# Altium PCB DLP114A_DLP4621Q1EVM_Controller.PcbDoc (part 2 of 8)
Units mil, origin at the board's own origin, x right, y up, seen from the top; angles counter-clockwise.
Board outline 4803.15 x 2598.43 mil, 14 copper layers (Top Layer, GND 1, SIGNAL 1, GND 2, SIGNAL 2, PWR SPLIT PLANE 1, GND 3, GND 4, PWR SPLIT PLANE 2, SIGNAL 3, GND 5, SIGNAL 4, GND 6, Bottom Layer), stack 91.4 mil thick; 489 components, 394 nets, 1925 pads, 1273 vias.
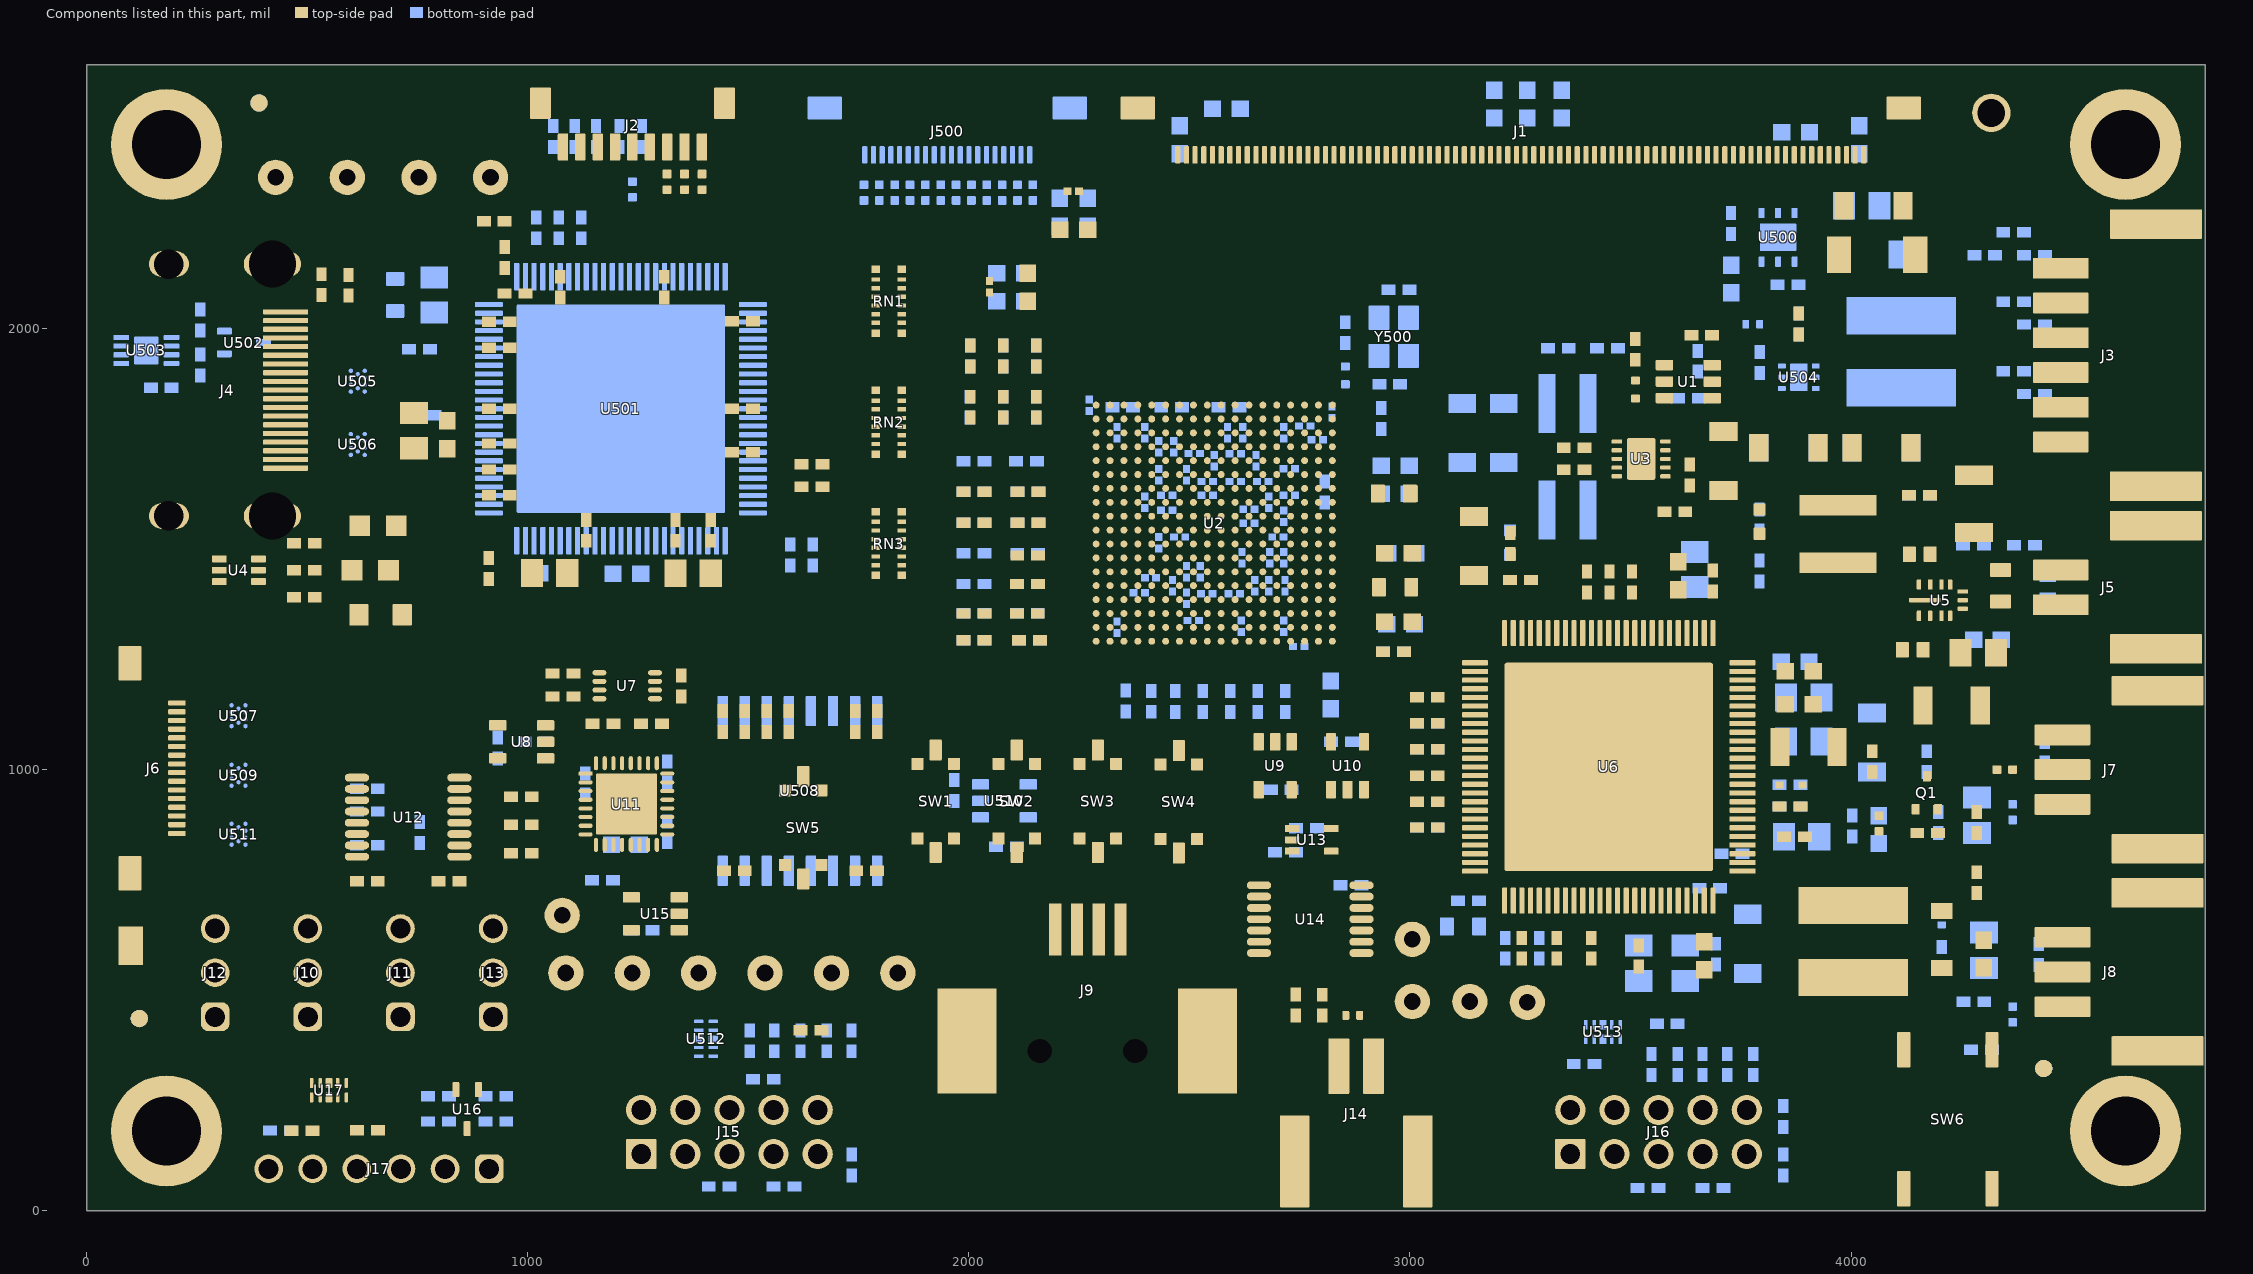
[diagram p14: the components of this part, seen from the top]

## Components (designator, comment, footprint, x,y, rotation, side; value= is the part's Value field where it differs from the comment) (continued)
R34 "CRCW0402150RFKED" 0402 493.55,1391.12 r180 top locked value=150
R35 "ERJ-2GEJ103X" 0402 2011.4,1354.08 r0 top locked value=10k
R36 "ERJ-2RKF33R0X" 0402 2132.51,1354.08 r180 top locked value=33.0
R37 "CRCW04022K20JNED" 0402 2011.4,1293.01 r180 top locked value=2.2k
R38 "CRCW04022K20JNED" 0402 2137.51,1293.01 r180 top locked value=2.2k
R39 "ERJ-2RKF33R0X" 0402 2962.37,1267.65 r180 top locked value=33.0
R40 "ERJ-2GEJ103X" 0402 1080.18,1218.07 r0 top locked value=10k
R41 "ERJ-2GEJ103X" 0402 3039.25,1163.8 r0 top locked value=10k
R42 "ERJ-2GEJ103X" 0402 1742.05,1109.51 r270 top locked value=10k
R43 "ERJ-2GEJ103X" 0402 1792.05,1109.51 r270 top locked value=10k
R44 "CRCW04023K30JNED" 0402 1442.05,1109.51 r270 top locked value=3.3k
R45 "ERJ-2GEJ103X" 0402 1542.05,1109.51 r270 top locked value=10k
R46 "CRCW04021K00FKED" 0402 1592.05,1109.51 r270 top locked value=1.00k
R47 "ERJ-2GEJ103X" 0402 3039.25,1105.2 r0 top locked value=10k
R48 "ERJ-2GEJ103X" 0402 1170.49,1104.45 r0 top locked value=10k
R49 "ERJ-2GEJ103X" 0402 1280.49,1104.45 r180 top locked value=10k
R50 "CRCW04021K00FKED" 0402 3039.25,1046.6 r0 top locked value=1.00k
R51 "ERJ-2RKF33R0X" 0402 985.47,939.01 r180 top locked value=33.0
R52 "ERJ-2GEJ103X" 0402 3039.25,927.58 r0 top locked value=10k
R53 "ERJ-2RKF33R0X" 0402 985.47,874.98 r180 top locked value=33.0
R54 "ERJ-2GEJ103X" 0402 3039.25,868.98 r0 top locked value=10k
R55 "ERJ2RKF1802X" 0402 4173.67,856.62 r0 top locked value=18.0k
R56 "ERJ-2RKF33R0X" 0402 985.47,810.94 r180 top locked value=33.0
R57 "CRCW040210R0FKED" 0402 4285.15,744 r90 top locked value=10.0
R58 "CRCW04023K30JNED" 0402 1768.43,770.93 r180 top locked value=3.3k
R59 "ERJ-2GEJ103X" 0402 1468.43,770.93 r180 top locked value=10k
R60 "ERJ-2GEJ103X" 0402 821.44,746.73 r180 top locked value=10k
R61 "ERJ-2GEJ103X" 0402 3253.82,595.29 r90 top locked value=10k
R62 "ERJ-2RKF33R0X" 0402 3332.56,595.29 r90 top locked value=33.0
R63 "ERJ-2GEJ103X" 0402 2741.35,466.78 r90 top locked value=10k
R64 "ERJ-2RKF33R0X" 0402 2801.2,466.34 r270 top locked value=33.0
R65 "ERJ-2GEJ103X" 0402 1642.03,409.02 r180 top locked value=10k
R500 "CRCW04020000Z0EDHP" 0402 3727.75,2237.97 r270 bottom locked value=0
R501 "ERJ-2GEJ103X" 0402 1121.46,2228.35 r90 bottom locked value=10k
R502 "ERJ-2GEJ103X" 0402 1070.46,2228.35 r90 bottom locked value=10k
R503 "ERJ-2GEJ103X" 0402 1019.46,2228.35 r90 bottom locked value=10k
R504 "CRCW04026K81FKED" 0402 4368.58,2218.21 r180 bottom locked value=6.81k
R505 "ERJ-2GEJ103X" 0402 3857.09,2098.95 r0 bottom locked value=10k
R506 "CRCW04026K81FKED" 0402 4368.58,2060.73 r180 bottom locked value=6.81k
R507 "CRCW04022K20JNED" 0402 257.96,2019.65 r90 bottom locked value=2.2k
R508 "CRCW040243K2FKED" 0402 3881.47,2010.55 r90 bottom locked value=43.2k
R509 "CRCW04021M00FKED" 0402 2853.2,1990.69 r90 bottom locked value=1.00Meg
R510 "ERJ-2GEJ103X" 0402 2152.78,1937.94 r270 bottom locked value=10k
R511 "ERJ-2GEJ103X" 0402 2077.78,1937.94 r270 bottom locked value=10k
R512 "ERJ-2GEJ103X" 0402 2002.79,1937.94 r270 bottom locked value=10k
R513 "ERJ-2RKF3603X" 0402 3336.29,1955.26 r180 bottom locked value=360k
R514 "RC0402FR-07180KL" 0402 3447.62,1955.24 r180 bottom locked value=180k
R515 "ERJ-2GEJ103X" 0402 754.84,1953.52 r180 bottom locked value=10k
R516 "CRCW04024R99FKED" 0402 3652.59,1926.01 r90 bottom locked value=4.99
R517 "CRCW04025K11FKED" 0402 3792.63,1923.29 r270 bottom locked value=5.11k
R518 "CRCW04022K20JNED" 0402 257.96,1917.22 r270 bottom locked value=2.2k
R519 "CRCW04026K81FKED" 0402 4368.58,1903.25 r180 bottom locked value=6.81k
R520 "3K" FP-ERJ-2RKF3001X_0402-MFG 2853.64,1893.84 r90 bottom locked value=3k
R521 "ERJ-2RKF33R0X" 0402 2152.78,1821.94 r90 bottom locked value=33.0
R522 "ERJ-2RKF33R0X" 0402 2077.78,1821.94 r90 bottom locked value=33.0
R523 "ERJ-2RKF33R0X" 0402 2002.26,1821.94 r90 bottom locked value=33.0
R524 "CRCW04020000Z0EDHP" 0402 3630.94,1842.39 r180 bottom locked value=0
R525 "CRCW040242K2FKED" 0402 2935.04,1795.96 r270 bottom locked value=42.2k
R526 "CRCW04022K20JNED" 0402 2589.91,1821.42 r180 bottom locked value=2.2k
R527 "CRCW040242K2FKED" 0402 2459.74,1821.42 r0 bottom locked value=42.2k
R528 "CRCW040242K2FKED" 0402 2348.83,1821.42 r0 bottom locked value=42.2k
R529 "ERJ-2GEJ103X" 0402 2130.79,1699.32 r0 bottom locked value=10k
R530 "ERJ-2RKF33R0X" 0402 2011.4,1699.32 r0 bottom locked value=33.0
R531 "CRCW04021K00FKED" 0402 2806.57,1629.75 r90 bottom locked value=1.00k
R532 "ERJ-2RKF33R0X" 0402 2133.94,1629.72 r180 bottom locked value=33.0
R533 "ERJ-2GEJ103X" 0402 2011.4,1629.72 r0 bottom locked value=10k
R534 "CRCW04020000Z0EDHP" 0402 4154.95,1622.25 r0 bottom locked value=0
R535 "ERJ-2GEJ104X" 0402 3792.3,1566.26 r90 bottom locked value=100k
R536 "ERJ-2GEJ103X" 0402 2133.94,1560.12 r0 bottom locked value=10k
R537 "ERJ-2GEJ103X" 0402 2011.4,1560.12 r0 bottom locked value=10k
R538 "ERJ-2RKF33R0X" 0402 1646.45,1486.66 r270 bottom locked value=33.0
R539 "ERJ-2RKF33R0X" 0402 1595.45,1486.66 r270 bottom locked value=33.0
R540 "CRCW0402511KFKED" 0402 4277.26,1508.87 r180 bottom locked value=511k
R541 "ERJ-2RKF1543X" 0402 4392.9,1508.4 r180 bottom locked value=154k
R542 "ERJ-2GEJ103X" 0402 2133.44,1490.52 r0 bottom locked value=10k
R543 "ERJ-2GEJ103X" 0402 2011.4,1490.52 r0 bottom locked value=10k
R544 "CRCW040243K2FKED" 0402 3792.3,1450.26 r90 bottom locked value=43.2k
R545 "ERJ-2GEJ103X" 0402 2132.8,1420.91 r0 bottom locked value=10k
R546 "ERJ-2RKF33R0X" 0402 2011.4,1420.91 r180 bottom locked value=33.0
R547 "ERJ-2GEJ103X" 0402 2011.4,1354.31 r0 bottom locked value=10k
R548 "ERJ-2GEJ103X" 0402 2132.51,1354.31 r0 bottom locked value=10k
R549 "CRCW04022K20JNED" 0402 2137.51,1293.01 r180 bottom locked value=2.2k
R550 "ERJ-2GEJ103X" 0402 2011.4,1293.01 r0 bottom locked value=10k
R551 "ERJ-2GEJ103X" 0402 2962.37,1267.65 r0 bottom locked value=10k
R552 "CRCW04022K20JNED" 0402 2355.62,1155.83 r270 bottom locked value=2.2k
R553 "CRCW04022K20JNED" 0402 2413.24,1154.98 r270 bottom locked value=2.2k
R554 "CRCW04021K00FKED" 0402 2467.76,1154.69 r90 bottom locked value=1.00k
R555 "ERJ-2RKF33R0X" 0402 2717.02,1154.69 r90 bottom locked value=33.0
R556 "CRCW04022K20JNED" 0402 2654.71,1154.69 r270 bottom locked value=2.2k
R557 "CRCW04022K20JNED" 0402 2592.39,1154.69 r270 bottom locked value=2.2k
R558 "CRCW04021K00FKED" 0402 2530.07,1154.69 r90 bottom locked value=1.00k
R559 "ERJ-2GEJ103X" 0402 3039.25,1105.2 r0 bottom locked value=10k
R560 "ERJ-2GEJ103X" 0402 1016.82,1063.12 r180 bottom locked value=10k
R561 "ERJ-2GEJ103X" 0402 3039.25,1046.6 r180 bottom locked value=10k
R562 "ERJ-2GEJ203X" 0402 4171.7,1018.12 r270 bottom locked value=20k
R563 "CRCW040230K0FKED" 0402 3861.41,965.59 r0 bottom locked value=30.0k
R564 "ERJ-2RKF33R0X" 0402 636.4,956.43 r0 bottom locked value=33.0
R565 "ERJ-2RKF1002X" 0402 3861.41,916.58 r180 bottom locked value=10.0k
R566 "CRCW0402162RFKED" 0402 4197.29,880.24 r270 bottom locked value=162
R567 "ERJ-2RKF33R0X" 0402 636.4,905.25 r0 bottom locked value=33.0
R568 "ERJ-2RKF33R0X" 0402 754.95,857.42 r270 bottom locked value=33.0
R569 "ERJ-2GEJ103X" 0402 3039.25,868.98 r0 bottom locked value=10k
R570 "ERJ-2GEJ103X" 0402 2717.98,812.52 r0 bottom value=10k
R571 "ERJ-2GEJ103X" 0402 2085.18,825.77 r0 bottom locked value=10k
R572 "ERJ-2GEJ103X" 0402 1169.56,749.74 r180 bottom locked value=10k
R573 "ERJ-2GEJ104X" 0402 3679.56,731.41 r0 bottom locked value=100k
R574 "ERJ-2GEJ103X" 0402 3293.19,595.29 r90 bottom locked value=10k
R575 "ERJ-2GEJ103X" 0402 3216.44,595.29 r90 bottom locked value=10k
R576 "CRCW040251K1FKED" 0402 3693.66,581.89 r90 bottom locked value=51.1k
R577 "CRCW04021K00FKED" 0402 4205.39,574.36 r270 bottom locked value=1.00k
R578 "CRCW040251K1FKED" 0402 4278.09,474.26 r0 bottom locked value=51.1k
R579 "ERJ-2GEJ103X" 0402 3583.18,423.69 r0 bottom locked value=10k
R580 "ERJ-2GEJ103X" 0402 1733.91,385.4 r90 bottom locked value=10k
R581 "CRCW040275R0FKED" 0402 1677.91,385.4 r90 bottom locked value=75.0
R582 "CRCW040275R0FKED" 0402 1618.4,385.4 r90 bottom locked value=75.0
R583 "CRCW040275R0FKED" 0402 1558.9,385.4 r90 bottom locked value=75.0
R584 "ERJ-2GEJ103X" 0402 1502.9,385.4 r90 bottom locked value=10k
R585 "CRCW04022K20JNED" 0402 4295.77,365.19 r180 bottom locked value=2.2k
R586 "CRCW040275R0FKED" 0402 3607.2,331.79 r90 bottom locked value=75.0
R587 "CRCW040275R0FKED" 0402 3547.48,331.79 r90 bottom locked value=75.0
R588 "CRCW040275R0FKED" 0402 3719.2,331.79 r90 bottom locked value=75.0
R589 "CRCW040275R0FKED" 0402 3663.2,331.79 r90 bottom locked value=75.0
R590 "ERJ-2GEJ103X" 0402 3778.03,331.77 r270 bottom locked value=10k
R591 "ERJ-2GEJ103X" 0402 3394.77,332.78 r0 bottom locked value=10k
R592 "CRCW04021K00FKED" 0402 927.67,259.94 r0 bottom locked value=1.00k
R593 "CRCW04021K00FKED" 0402 797.48,259.94 r180 bottom locked value=1.00k
RN1 "EXB-2HV330JV" RESCAXS_EXB-2HV 1818.38,2062.14 r270 top locked value=33
RN2 "EXB-2HV330JV" RESCAXS_EXB-2HV 1818.38,1787.47 r270 top locked value=33
RN3 "EXB-2HV330JV" RESCAXS_EXB-2HV 1818.38,1512.8 r270 top locked value=33
SW1 "CVS-01TB" FP-CVS-01TB_SMT_SW_4MM7_2MM0-MFG 1924.78,928.53 r0 top locked
SW2 "CVS-01TB" FP-CVS-01TB_SMT_SW_4MM7_2MM0-MFG 2108.66,928.53 r0 top locked
SW3 "CVS-01TB" FP-CVS-01TB_SMT_SW_4MM7_2MM0-MFG 2292.55,928.53 r0 top locked
SW4 "CVS-01TB" FP-CVS-01TB_SMT_SW_4MM7_2MM0-MFG 2476.09,927.34 r0 top locked
SW5 "CVS-01TB" FP-CVS-01TB_SMT_SW_4MM7_2MM0-MFG 1624.53,868.53 r0 top locked
SW6 "GT12MSABETR" FP-GT12MSABETR_SMT_7MM01_6MM93-MFG 4219.39,83.22 r90 top locked
TP1 "TESTPOINT" TESTPOINT 428.53,2342.8 r270 top locked
TP2 "TESTPOINT" TESTPOINT 590.93,2342.8 r270 top locked
TP3 "TESTPOINT" TESTPOINT 753.33,2342.8 r180 top locked
TP4 "TESTPOINT" TESTPOINT 915.73,2342.8 r180 top locked
TP5 "TESTPOINT" TESTPOINT 1078.22,669.94 r0 top locked
TP6 "TESTPOINT" TESTPOINT 3005.3,615.56 r0 top locked
TP7 "TESTPOINT" TESTPOINT 1086.46,539.32 r0 top locked
TP8 "TESTPOINT" TESTPOINT 1236.97,539.32 r90 top locked
TP9 "TESTPOINT" TESTPOINT 1387.48,539.32 r90 top locked
TP10 "TESTPOINT" TESTPOINT 1537.99,539.32 r0 top locked
TP11 "TESTPOINT" TESTPOINT 1688.5,539.32 r90 top locked
TP12 "TESTPOINT" TESTPOINT 1839.01,539.32 r90 top locked
TP13 "TESTPOINT" TESTPOINT 3005.3,474.4 r0 top locked
TP14 "TESTPOINT" TESTPOINT 3135.69,474.4 r90 top locked
TP15 "TESTPOINT" TESTPOINT 3266.08,472.65 r90 top locked
TP16 "S2751-46R" Harwin_S2751-46R 99.95,600.86 r90 top
TP17 "5007" Keystone5007 4317.81,2488.89 r0 top
U1 "TPS22918TDBVRQ1" DBV0006A_N 3630.94,1879.79 r180 top locked
U2 "DLPC231" ZEK0324A-MFG 2556.29,1558.89 r0 top locked
U3 "TPS62420QDRCRQ1" DRC0010J 3523.99,1704.49 r180 top locked
U4 "SN74LVC2G06QDCKRQ1" DCK0006A_N 345.17,1452.14 r0 top locked
U5 "LMR34215FAQRNX" RNX0012B 4197.98,1384.35 r90 top locked
U6 "TPS9900TPZPRQ1" PZP0100K 3450.67,1006.32 r0 top locked
U7 "TXS0102QDCURQ1" DCU0008A_N 1225.49,1190.38 r180 top locked
U8 "SN74LVC1G07QDBVRQ1" DBV0005A_N 986.31,1063.12 r180 top locked
U9 "74CBTLV1G125DBVRQ1" DBV0005A_N 2694.46,1008.97 r270 top locked
U10 "74CBTLV1G125DBVRQ1" DBV0005A_N 2858.34,1008.97 r90 top locked
U11 "CY7C65215-32LTXI" FP-CY7C65215-32LTXI_QFN32-IPC_C 1223.74,922.14 r0 top
U12 "SN74AVC4T774PWR" PW0016A_N 728.92,892.45 r180 top locked
U13 "SN74LVC1G04QDCKRQ1" DCK0005A_N 2777.19,841.06 r0 top locked
U14 "SN74LVC08AQPWRQ1" PW0014A_N 2773.82,661.12 r0 top locked
U15 "SN74LVC1G07QDBVRQ1" DBV0005A_N 1289.3,673.33 r180 top locked
U16 "TPD2E2U06QDCKRQ1" DCK0003A_N 862.58,230.65 r270 top locked
U17 "TPD4E05U06QDQARQ1" DQA0010A#1 549.37,273.45 r90 top locked
U500 "LP38693SD-3.3/NOPB" NGG0006A 3834.53,2206.85 r90 bottom locked
U501 "TFP401AIPZPRQ1" PZP0100H-MFG 1211.32,1818.32 r270 bottom locked
U502 "TPD2E2U06QDCKRQ1" DCK0003A_N 356.7,1968.44 r0 bottom locked
U503 "AT34C02D-MAHM-T" FP-AT34C02D-MAHM-T_UDFN8-MFG 135.48,1950.36 r0 bottom locked
U504 "TPS61170QDRVRQ1" DRV0006A 3881.47,1889.67 r0 bottom locked
U505 "PCMF2HDMI2SZ" FP-PCMF2HDMI2SZ_WLCSP10-MFG 614.77,1880.68 r270 bottom locked
U506 "PCMF2HDMI2SZ" FP-PCMF2HDMI2SZ_WLCSP10-MFG 614.77,1737.27 r270 bottom locked
U507 "PCMF2HDMI2SZ" FP-PCMF2HDMI2SZ_WLCSP10-MFG 344.42,1122.45 r270 bottom locked
U508 "MT25QL128ABA8ESF-0AAT" FP-MT25QL128ABA8ESF-0AAT_SOP2-16-MFG 1617.05,952.03 r270 bottom locked
U509 "PCMF2HDMI2SZ" FP-PCMF2HDMI2SZ_WLCSP10-MFG 344.42,987.44 r270 bottom locked
U510 "74CBTLV1G125DBVRQ1" DBV0005A_N 2080.49,929.27 r0 bottom locked
U511 "PCMF2HDMI2SZ" FP-PCMF2HDMI2SZ_WLCSP10-MFG 344.42,853.72 r270 bottom locked
U512 "TPD4E05U06QDQARQ1" DQA0010A#2 1404.29,389.93 r180 bottom locked
U513 "TPD4E05U06QDQARQ1" DQA0010A#2 3437.55,405.41 r90 bottom locked
Y500 "AM16070006" FP-AM16070006_SMT_XTAL_3MM2_2MM5-MFG 2963.05,1981.26 r270 bottom locked
ZZ1 "This Assembly Note is for PCB labels only" AssemblyNoteLabel 483.35,8777.95 r0 top
ZZ2 "These assemblies are ESD sensitive, ESD precautions shall be observed." AssemblyNote 483.35,8681.72 r0 top
ZZ3 "These assemblies must be clean and free from flux and all contaminants. Use of no clean flux is not acceptable." AssemblyNote 483.35,8585.49 r0 top
ZZ4 "These assemblies must comply with workmanship standards IPC-A-610 Class 2, unless otherwise specified." AssemblyNote 483.35,8489.26 r0 top
ZZ5 "Indication provided for the D* components at their cathode side." AssemblyNote 483.35,8393.03 r0 top

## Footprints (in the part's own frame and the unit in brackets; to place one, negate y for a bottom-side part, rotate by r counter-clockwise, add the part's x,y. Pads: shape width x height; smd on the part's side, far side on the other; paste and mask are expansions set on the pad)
0201_033 [mm] "SMD, 2-Leads, Height 0.33mm"
  rect 0.46x0.42 smd mask+0.048: 1(-0.33,0) 2(0.33,0)
  body extent -0.31,-0.16 0.31,0.16, height 0.33
0402 [mm] "0402 from SM-752 data"
  rect 0.8x0.6 smd: 1(-0.6,0) 2(0.6,0)
  silkscreen extent -1.22,-0.52 1.22,0.52, body extent -0.55,-0.3 0.55,0.3, height 0.6
0603 [mm] "0603 from SM-752 data"
  rect 1x0.95 smd: 1(-0.8,0) 2(0.8,0)
  silkscreen extent -1.52,-0.69 1.52,0.69, body extent -0.87,-0.47 0.87,0.47, height 1
0805_HV [mil] "0805 with 30mil clearance between pads"
  rect 50x63 smd: 1(-40,0) 2(40,0)
  silkscreen extent -74,-40 74,40, body extent -43,-29 43,29, height 57
1206_180 [mm] "1206_180"
  rect 1.1x1.6 smd: 1(-1.7,0) 2(1.7,0)
  silkscreen extent -0.9,-1 0.9,1, body extent -1.75,-0.95 1.75,0.95, height 1.8
1210_280 [mm] "SMD, 2-Leads, Body 3.6x2.8mm, Height 2.8mm"
  rect 1.1x2.2 smd: 1(-1.65,0) 2(1.65,0)
  silkscreen extent -0.84,-1.4 0.84,1.4, body extent -1.8,-1.4 1.8,1.4, height 2.8
AssemblyNote [mil] "Assembly Note"
AssemblyNoteLabel [mil] "Assembly Note for PCB Labels"
CDRH5D18 [mm] "Sumida recommended land pattern"
  rect 2.15x6.3 smd: 1(-2.075,0) 2(2.075,0)
  silkscreen extent -3.62,-3.56 3.64,3.57, body extent -3,-3 3,3, height 2
CE_Mark_5mm [mil] "Minimum text height for CE Mark"
  silkscreen extent -138,-98 138,98
CONN_USB-1734346 [mm] "TE Connectivity"
  rect 3x0.7 smd: 1(-3.5,1.9) 2(-3.5,-0.6) 3(-3.5,-1.85) 4(-3.5,0.65)
  rect 6.04x3.4 smd: 5(2.92,-6.92) 6(2.92,6.92)
  round 1 hole 1.4 unplated: MH1(3.5,2.75) MH2(3.5,-2.75)
  silkscreen extent -3.8,-6.4 12.7,6.4, body extent -4.6,-8.22 12.5,8.28, height 11.31
DBV0005A_N [mm] "SOT23, 5-Leads, Body 2.9x1.6mm, Pitch 0.95mm, Lead Span 2.8mm, IPC Medium Density"
  rrect17% 1x0.6 smd: 1(-1.375,0.95) 2(-1.375,0) 3(-1.375,-0.95) 4(1.375,-0.95) 5(1.375,0.95)
  silkscreen extent -1.63,-1.55 0.38,1.55, body extent -1.42,-1.46 1.42,1.46, height 1.09
DBV0006A_N [mm] "SOT23, 6-Leads, Body 2.9x1.6mm, Pitch 0.95mm, Lead Span 2.8mm, IPC Medium Density"
  rrect17% 1x0.6 smd: 1(-1.375,0.95) 2(-1.375,0) 3(-1.375,-0.95) 4(1.375,-0.95) 5(1.375,0) 6(1.375,0.95)
  silkscreen extent -1.67,-1.55 0.5,1.55, body extent -1.42,-1.46 1.42,1.46, height 1.12
DCK0003A_N [mm] "SOT23, 3-Leads, Body 2.0x1.25mm, Pitch 0.65mm, Lead Span 2.1mm, IPC Medium Density"
  rrect25% 0.85x0.4 smd: 1(-1.125,0.65) 2(-1.125,-0.65) 3(1.125,0)
  silkscreen extent -1.02,-1.1 0.7,1.53, body extent -1.06,-1 1.06,1, height 1.1
DCK0005A_N [mm] "SOT353, 5-Leads, Body 2x1.3mm, Pitch 0.65mm, Lead Span 2.1mm, IPC Medium Density"
  rrect25% 0.85x0.4 smd: 1(-1.125,0.65) 2(-1.125,0) 3(-1.125,-0.65) 4(1.125,-0.65) 5(1.125,0.65)
  silkscreen extent -1.48,-1.02 0.55,1.1, body extent -1.14,-1 1.14,1, height 0.95
DCK0006A_N [mm] "SOT23, 6-Leads, Body 2x1.3mm, Pitch 0.65mm, Lead Span 2.1mm, IPC Medium Density"
  rrect25% 0.85x0.4 smd: 1(-1.125,0.65) 2(-1.125,0) 3(-1.125,-0.65) 4(1.125,-0.65) 5(1.125,0) 6(1.125,0.65)
  silkscreen extent -1.5,-1.09 0.51,1.09, body extent -1.14,-1 1.14,1, height 0.95
DCU0008A_N [mm] "TSSOP, 8-Leads, Body 2x2.3mm, Pitch 0.5mm, IPC Medium Density"
  oval 0.8x0.3 smd: 1(-1.6,0.75) 2(-1.6,0.25) 3(-1.6,-0.25) 4(-1.6,-0.75) 5(1.6,-0.75) 6(1.6,-0.25) 7(1.6,0.25) 8(1.6,0.75)
  silkscreen extent -1.05,-1.05 0.38,1.05, body extent -1.56,-1 1.56,1, height 0.9
DQA0010A#1 [mm] "SON, 10-Leads, Body 1x2.5mm, Pitch 0.5mm, TI Recommended"
  rrect50% 0.565x0.2 smd: 1(-0.417,1) 2(-0.417,0.5) 4(-0.417,-0.5) 5(-0.417,-1) 6(0.417,-1) 7(0.417,-0.5) 9(0.417,0.5) 10(0.417,1)
  rrect28% 0.565x0.36 on Top Paste: 3(-0.417,0) 8(0.417,0)
  rrect25% 0.565x0.4 smd paste-0.2: 3(-0.417,0) 8(0.417,0)
  silkscreen extent -0.67,-1.45 0.55,1.45, body extent -0.55,-1.3 0.55,1.3, height 0.56
DQA0010A#2 [mm] "SON, 10-Leads, Body 1x2.5mm, Pitch 0.5mm, TI Recommended"
  rrect50% 0.565x0.2 smd: 1(-0.417,1) 2(-0.418,0.5) 4(-0.418,-0.5) 5(-0.417,-1) 6(0.417,-1) 7(0.418,-0.5) 9(0.417,0.5) 10(0.417,1)
  rrect28% 0.565x0.36 on Bottom Paste: 3(-0.418,0) 8(0.417,0)
  rrect25% 0.565x0.4 smd paste-0.2: 3(-0.418,0) 8(0.417,0)
  silkscreen extent -0.67,-1.45 0.55,1.45, body extent -0.55,-1.3 0.55,1.3, height 0.56
DRC0010J [mm] "VSON-10"
  rrect42% 0.6x0.24 smd: 1(-1.4,1) 2(-1.4,0.5) 3(-1.4,0) 4(-1.4,-0.5) 5(-1.4,-1) 6(1.4,-1) 7(1.4,-0.5) 8(1.4,0) 9(1.4,0.5) 10(1.4,1)
  rrect12% 1.65x2.4 smd paste-1 mask-2: 11(0,0)
  Top Layer region: -0.375,-1.65 -0.375,-1.2 -0.775,-1.2 -0.794,-1.196 -0.81,-1.185 -0.821,-1.169 -0.825,-1.15 -0.825,-1.15 -0.825,1.15 -0.821,1.169 -0.81,1.185 -0.794,1.196 -0.775,1.2 -0.775,1.2 -0.375,1.2 -0.375,1.65 -0.371,1.669 -0.36,1.685 -0.344,1.696 -0.325,1.7 -0.325,1.7 -0.325,1.7 -0.175,1.7 -0.175,1.7 -0.156,1.696 -0.14,1.685 -0.129,1.669 -0.125,1.65 -0.125,1.65 -0.125,1.2 0.125,1.2 0.125,1.65 0.129,1.669 0.14,1.685 0.156,1.696 0.175,1.7 0.175,1.7 0.175,1.7 0.325,1.7 0.325,1.7 0.344,1.696 0.36,1.685 0.371,1.669 0.375,1.65 0.375,1.65 0.375,1.2 0.775,1.2 0.794,1.196 0.81,1.185 0.821,1.169 0.825,1.15 0.825,1.15 0.825,-1.15 0.821,-1.169 0.81,-1.185 0.794,-1.196 0.775,-1.2 0.775,-1.2 0.375,-1.2 0.375,-1.65 0.371,-1.669 0.36,-1.685 0.344,-1.696 0.325,-1.7 0.325,-1.7 0.175,-1.7 0.156,-1.696 0.14,-1.685 0.129,-1.669 0.125,-1.65 0.125,-1.65 0.125,-1.2 -0.125,-1.2 -0.125,-1.65 -0.129,-1.669 -0.14,-1.685 -0.156,-1.696 -0.175,-1.7 -0.175,-1.7 -0.325,-1.7 -0.344,-1.696 -0.36,-1.685 -0.371,-1.669 -0.375,-1.65
  body extent -1.5,-1.5 1.5,1.5, height 1
DRV0006A [mm] "SON, 6-Leads, Body 2x2mm, Pitch 0.65mm, Thermal Pad 1.6x1mm, TI Recommended"
  rrect33% 0.45x0.3 smd: 1(-0.975,0.65) 2(-0.975,0) 3(-0.975,-0.65) 4(0.975,-0.65) 5(0.975,0) 6(0.975,0.65)
  rrect14% 1x0.7 on Bottom Paste: 7(0,-0.45) 7(0,0.45)
  rrect10% 1x1.6 smd paste-0.5: 7(0,0)
  silkscreen extent -1.05,-1.2 1.05,1.2, body extent -1.05,-1.05 1.05,1.05, height 0.81
ESD_Overlay_Small [mil]
  silkscreen extent -62,-48 64,61
FCC_disclaimer [mil]
Fiducial10-20 [mm]
  round 1 smd mask+0.5: 1(0,0)
  Top Layer keep-out circle w1.178: c0,0 r0.5
FP-501331-0907_HDR9-MFG [mm]
  rrect17% 0.6x1.55 smd paste+0 mask+0: 1(4,2.41) 2(3,2.41) 3(2,2.41) 4(1,2.41) 5(0,2.41) 6(-1,2.41) 7(-2,2.41) 8(-3,2.41) 9(-4,2.41)
  rrect8% 1.2x1.8 smd paste+0 mask+0: 10(-5.3,-0.115) 11(5.3,-0.115)
  silkscreen extent -5.6,-2.33 5.6,3.86, body extent -5.62,-2.24 5.62,2.83, height 5.6
FP-502352-0200_HDR2-MFG [mm]
  rrect8% 1.2x3.2 smd paste+0 mask+0: 1(-1,3.53) 2(1,3.53)
  rrect6% 1.7x5.3 smd paste+0 mask+0: 3(-3.55,-1.95) 4(3.55,-1.95)
  body extent -4,-4.7 4,4.7, height 6.6
FP-505110-1692_CONN_SMT_12MM7_5MM25-MFG [mm]
  rrect33% 0.3x1 smd paste+0 mask+0: 1(-3.75,2.475) 2(-3.25,2.475) 3(-2.75,2.475) 4(-2.25,2.475) 5(-1.75,2.475) 6(-1.25,2.475) 7(-0.75,2.475) 8(-0.25,2.475) 9(0.25,2.475) 10(0.75,2.475) 11(1.25,2.475) 12(1.75,2.475) 13(2.25,2.475) 14(2.75,2.475) 15(3.25,2.475) 16(3.75,2.475)
  rrect8% 2x1.3 smd paste+0 mask+0: 17(-6.05,-0.225) 18(6.05,-0.225)
  body extent -6.75,-2.63 6.75,2.67, height 1.9
FP-702461002_HDR10-MFG [mm]
  rrect6% 1.74x1.74 hole 1.14 paste-1000 mask+0: 1(-5.08,-1.275)
  round 1.74 hole 1.14 paste-1000 mask+0: 2(-5.08,1.265) 3(-2.54,-1.275) 4(-2.54,1.265) 5(0,-1.275) 6(0,1.265) 7(2.54,-1.275) 8(2.54,1.265) 9(5.08,-1.275) 10(5.08,1.265)
  silkscreen extent -10.26,-5.34 10.26,4.54, body extent -10.16,-4.45 10.16,4.44, height 9.47
FP-5023520200_HDR2-MFG [mm]
  rrect8% 1.2x3.2 smd paste+0 mask+0: 1(-1,3.53) 2(1,3.53)
  rrect6% 1.7x5.3 smd paste+0 mask+0: 3(-3.55,-1.95) 4(3.55,-1.95)
  silkscreen extent -4.1,-4.8 4.1,5.85, body extent -4,-4.7 4,4.7, height 6.6
FP-5023520600_HDR6-MFG [mm]
  rrect8% 1.2x3.2 smd paste+0 mask+0: 1(-5,3.53) 2(-3,3.53) 3(-1,3.53) 4(1,3.53) 5(3,3.53) 6(5,3.53)
  rrect6% 1.7x5.3 smd paste+0 mask+0: 7(-7.55,-1.95) 8(7.55,-1.95)
  silkscreen extent -8.13,1.07 8.13,5.72, body extent -8,-4.7 8,4.7, height 6.6
FP-5051102091_CONN_FFC_FPC20-MFG [mm]
  rrect33% 0.3x1 smd paste+0 mask+0: 1(-4.75,0.91) 2(-4.25,0.91) 3(-3.75,0.91) 4(-3.25,0.91) 5(-2.75,0.91) 6(-2.25,0.91) 7(-1.75,0.91) 8(-1.25,0.91) 9(-0.75,0.91) 10(-0.25,0.91) 11(0.25,0.91) 12(0.75,0.91) 13(1.25,0.91) 14(1.75,0.91) 15(2.25,0.91) 16(2.75,0.91) 17(3.25,0.91) 18(3.75,0.91) 19(4.25,0.91) 20(4.75,0.91)
  rrect8% 2x1.3 smd paste+0 mask+0: 21(-7.05,-1.79) 22(7.05,-1.79)
  silkscreen extent -7.45,-4.29 7.45,2.08, body extent -7.75,-4.19 7.75,1.11, height 2.1
FP-5051108091_CONN_FFC_FPC_80-MFG [mm]
  rrect33% 0.3x1 smd paste+0 mask+0: 1(-19.75,2.475) 2(-19.25,2.475) 3(-18.75,2.475) 4(-18.25,2.475) 5(-17.75,2.475) 6(-17.25,2.475) 7(-16.75,2.475) 8(-16.25,2.475) 9(-15.75,2.475) 10(-15.25,2.475) 11(-14.75,2.475) 12(-14.25,2.475) 13(-13.75,2.475) 14(-13.25,2.475) 15(-12.75,2.475) 16(-12.25,2.475) 17(-11.75,2.475) 18(-11.25,2.475) 19(-10.75,2.475) 20(-10.25,2.475) 21(-9.75,2.475) 22(-9.25,2.475) 23(-8.75,2.475) 24(-8.25,2.475) 25(-7.75,2.475) 26(-7.25,2.475) 27(-6.75,2.475) 28(-6.25,2.475) 29(-5.75,2.475) 30(-5.25,2.475) 31(-4.75,2.475) 32(-4.25,2.475) 33(-3.75,2.475) 34(-3.25,2.475) 35(-2.75,2.475) 36(-2.25,2.475) 37(-1.75,2.475) 38(-1.25,2.475) 39(-0.75,2.475) 40(-0.25,2.475) 41(0.25,2.475) 42(0.75,2.475) 43(1.25,2.475) 44(1.75,2.475) 45(2.25,2.475) 46(2.75,2.475) 47(3.25,2.475) 48(3.75,2.475) 49(4.25,2.475) 50(4.75,2.475) 51(5.25,2.475) 52(5.75,2.475) 53(6.25,2.475) 54(6.75,2.475) 55(7.25,2.475) 56(7.75,2.475) 57(8.25,2.475) 58(8.75,2.475) 59(9.25,2.475) 60(9.75,2.475) 61(10.25,2.475) 62(10.75,2.475) 63(11.25,2.475) 64(11.75,2.475) 65(12.25,2.475) 66(12.75,2.475) 67(13.25,2.475) 68(13.75,2.475) 69(14.25,2.475) 70(14.75,2.475) 71(15.25,2.475) 72(15.75,2.475) 73(16.25,2.475) 74(16.75,2.475) 75(17.25,2.475) 76(17.75,2.475) 77(18.25,2.475) 78(18.75,2.475) 79(19.25,2.475) 80(19.75,2.475)
  rrect8% 2x1.3 smd paste+0 mask+0: 81(-22.05,-0.225) 82(22.05,-0.225)
  silkscreen extent -22.45,-2.73 22.45,3.65, body extent -22.75,-2.63 22.75,2.68, height 2.1
FP-AM16070006_SMT_XTAL_3MM2_2MM5-MFG [mm]
  rrect8% 1.4x1.2 smd paste+0 mask+0: 1(-1.1,-0.85) 2(1.1,-0.85) 3(1.1,0.85) 4(-1.1,0.85)
  body extent -1.6,-1.25 1.6,1.25, height 0.8
FP-AT34C02D-MAHM-T_UDFN8-MFG [mm]
  rrect33% 0.9x0.3 smd paste+0 mask+0: 1(-1.45,0.75) 2(-1.45,0.25) 3(-1.45,-0.25) 4(-1.45,-0.75) 5(1.45,-0.75) 6(1.45,-0.25) 7(1.45,0.25) 8(1.45,0.75)
  rrect7% 1.4x1.6 smd paste+0 mask+0: 9(0,0)
  silkscreen extent -2.6,-1.3 1.55,1.3, body extent -1.51,-1 1.51,1, height 0.6
FP-C0603C223K1RACAUTO_0603-MFG [mm]
  rrect13% 0.75x0.9 smd paste+0 mask+0: 1(-0.6,0) 2(0.6,0)
  silkscreen extent -0.87,-0.85 0.88,0.85, body extent -1.2,-0.6 1.2,0.6, height 0.25
FP-CGA3E2C0G1H330J080AA_0603-MFG [mm]
  rrect14% 0.7x0.7 smd paste+0 mask+0: 1(-0.7,0) 2(0.7,0)
  silkscreen extent -0.95,-0.73 0.95,0.73, body extent -1.15,-0.65 1.15,0.65, height 0.25
FP-CGA4J1X7R0J106K125AC_0805-MFG [mm]
  rrect13% 0.8x1.05 smd paste+0 mask+0: 1(-0.925,0) 2(0.925,0)
  silkscreen extent -0.15,-0.73 0.15,0.73, body extent -1,-0.63 1,0.63, height 1.45
FP-CVS-01TB_SMT_SW_4MM7_2MM0-MFG [mm]
  rrect14% 0.7x1.2 smd paste+0 mask+0: 1(0,2.95) 2(0,-2.95)
  rrect14% 0.7x0.7 smd paste+0 mask+0: 3(-1.05,2.15) 4(1.05,2.15) 5(-1.05,-2.15) 6(1.05,-2.15)
  silkscreen extent -1.15,-1.43 1.15,4.22, body extent -1.5,-3.65 1.5,3.65, height 0.25
FP-CY7C65215-32LTXI_QFN32-IPC_C [mm]
  rrect42% 0.81x0.239 smd paste+0 mask+0: 1(-2.351,1.75)
  rrect100% 0.81x0.239 smd paste+0 mask+0: 2(-2.351,1.25) 3(-2.351,0.75) 4(-2.351,0.25) 5(-2.351,-0.25) 6(-2.351,-0.75) 7(-2.351,-1.25) 8(-2.351,-1.75) 17(2.351,-1.75) 18(2.351,-1.25) 19(2.351,-0.75) 20(2.351,-0.25) 21(2.351,0.25) 22(2.351,0.75) 23(2.351,1.25) 24(2.351,1.75)
  rrect100% 0.239x0.81 smd paste+0 mask+0: 9(-1.75,-2.351) 10(-1.25,-2.351) 11(-0.75,-2.351) 12(-0.25,-2.351) 13(0.25,-2.351) 14(0.75,-2.351) 15(1.25,-2.351) 16(1.75,-2.351) 25(1.75,2.351) 26(1.25,2.351) 27(0.75,2.351) 28(0.25,2.351) 29(-0.25,2.351) 30(-0.75,2.351) 31(-1.25,2.351) 32(-1.75,2.351)
  rrect3% 3.5x3.5 smd paste-1000 mask+0: 33(0,0)
  silkscreen extent -3.33,-2.5 2.5,2.5, body extent -2.86,-2.86 2.86,2.86, height 0.25
FP-ERJ-2RKF3000X_0402-MFG [mm]
  rrect21% 0.475x0.5 smd paste+0 mask+0: 1(-0.513,0) 2(0.513,0)
  silkscreen extent -0.52,-0.63 0.53,0.63, body extent -0.85,-0.38 0.85,0.38, height 0.25
FP-ERJ-2RKF3001X_0402-MFG [mm]
  rrect21% 0.475x0.5 smd paste+0 mask+0: 1(-0.513,0) 2(0.513,0)
  silkscreen extent -0.53,-0.63 0.53,0.63, body extent -0.5,-0.25 0.5,0.25, height 0.4
FP-GCM155R71H103KA55D_0402-MFG [mm]
  rrect25% 0.4x0.5 smd paste+0 mask+0: 1(-0.4,0) 2(0.4,0)
  silkscreen extent -0.53,-0.65 0.53,0.65, body extent -0.5,-0.25 0.5,0.25, height 0.55
FP-GT12MSABETR_SMT_7MM01_6MM93-MFG [mil]
  rrect13% 80x30 smd paste+0 mask+0: 1(281.96,-100) 3(281.96,100) 4(-33,100) 5(-33,-100)
  silkscreen extent -61,-138 349,138, body extent -215,-142 326,142, height 10
FP-HD04-19-TH-TR_CONN_HDMI_RCPT19-MFG [mm]
  rrect33% 0.3x2.6 smd paste+0 mask+0: 1(4.5,5.56) 2(4,5.56) 3(3.5,5.56) 4(3,5.56) 5(2.5,5.56) 6(2,5.56) 7(1.5,5.56) 8(1,5.56) 9(0.5,5.56) 10(0,5.56) 11(-0.5,5.56) 12(-1,5.56) 13(-1.5,5.56) 14(-2,5.56) 15(-2.5,5.56) 16(-3,5.56) 17(-3.5,5.56) 18(-4,5.56) 19(-4.5,5.56)
  rrect100% 1.5x3.3 hole 2.7 slot 0.9 at 0 deg paste-1000 mask+0: 20(-7.25,4.8) 21(7.25,4.8)
  rrect100% 1.5x2.3 hole 1.7 slot 0.9 at 0 deg paste-1000 mask+0: 22(-7.25,-1.16) 23(7.25,-1.16)
  silkscreen extent -7.75,-5.9 7.75,7.63, body extent -7.5,-5.8 7.5,6.4, height 6.46
FP-LTST-C171KRKT_0805-MFG [mm]
  rrect9% 1.1x1.25 smd paste+0 mask+0: 1(-1.25,0) 2(1.25,0)
  silkscreen extent -2.52,-0.68 0.33,0.67, body extent -1.9,-0.78 1.9,0.77, height 0.25
FP-MMZ1005Y121CTD25_0402-MFG [mm]
  rrect20% 0.5x0.5 smd paste+0 mask+0: 1(-0.45,0) 2(0.45,0)
  body extent -0.5,-0.25 0.5,0.25, height 0.55
FP-MPZ2012S101ATD25_0805-MFG [mm]
  rrect13% 0.8x1.2 smd paste+0 mask+0: 1(-0.9,0) 2(0.9,0)
  silkscreen extent -0.13,-0.73 0.13,0.73, body extent -1.4,-0.82 1.4,0.82, height 0.25
FP-MT25QL128ABA8ESF-0AAT_SOP2-16-MFG [mm]
  rrect17% 1.75x0.6 smd paste+0 mask+0: 1(-4.6,4.445) 2(-4.6,3.175) 3(-4.6,1.905) 4(-4.6,0.635) 5(-4.6,-0.635) 6(-4.6,-1.905) 7(-4.6,-3.175) 8(-4.6,-4.445) 9(4.6,-4.445) 10(4.6,-3.175) 11(4.6,-1.905) 12(4.6,-0.635) 13(4.6,0.635) 14(4.6,1.905) 15(4.6,3.175) 16(4.6,4.445)
  body extent -5.16,-5.15 5.16,5.15, height 2.65
FP-PCMF2HDMI2SZ_WLCSP10-MFG [mm]
  round 0.25 smd paste+0 mask-1000: A1(-0.6,0.4) A2(-0.2,0.4) A3(0.2,0.4) A4(0.6,0.4) B1(-0.4,0) B2(0.4,0) C1(-0.6,-0.4) C2(-0.2,-0.4) C3(0.2,-0.4) C4(0.6,-0.4)
  silkscreen extent -1.1,-0.9 1.1,1.5, body extent -0.78,-0.59 0.78,0.59, height 0.6
FP-SZMM5Z6V2T1G_SOD523-MFG [mm]
  rrect25% 0.48x0.4 smd paste+0 mask+0: 1(-0.66,0) 2(0.66,0)
  silkscreen extent -1.62,-0.45 0.05,0.45, body extent -1,-0.55 1,0.55, height 0.25
Harwin_S2751-46R [mm] "Test Point, SMT"
  rect 2.2x1.4 smd: 1(0,0)
  body extent -1,-0.6 1,0.6, height 1.4
Keystone5007 [mil] "Keystone Compact loops"
  round 87 hole 63: 1(0,0)
  silkscreen extent -70,-70 70,70, body extent -63,-63 62,63, height 225
LED_LTST-C171 [mm] "LITE-ON"
  rect 1.2x1.2 smd: 1(-1.05,0) 2(1.05,0)
  silkscreen extent -1.6,-1 2.2,1, body extent -1.05,-0.68 1.05,0.67, height 0.8
Molex_502352-0300 [mm] "Header(shrouded), 2mm, 3x1, R/A, SMT"
  rrect8% 1.2x3.2 smd: 1(-2,3.53) 2(0,3.53) 3(2,3.53)
  rrect6% 1.7x5.3 smd: MP1(-4.55,-1.95) MP2(4.55,-1.95)
  silkscreen extent -5,-4.7 5,5, body extent -5,-4.7 5,4.7, height 6.46
MTGP_252mil_157mil_6Via [mil] "4-40 Mounting Hole, Plated, for Pan Head"
  round 252 hole 157: 1(0,0)
NGG0006A [mm] "TI recommended footprint"
  rrect29% 0.6x0.35 smd: 1(-1.4,0.95) 2(-1.4,0) 3(-1.4,-0.95) 4(1.4,-0.95) 5(1.4,0) 6(1.4,0.95)
  rrect11% 1.47x0.94 on Bottom Paste: 7(0,0.57) 7(0,-0.57)
  rrect6% 1.6x2.1 smd paste-1: 7(0,0)
  silkscreen extent -1.65,-1.65 1.65,1.65, body extent -1.5,-1.5 1.5,1.5, height 0.81
PW0014A_N [mm] "TSOP, 14-Leads, Body 5x4.4mm, Pitch 0.65mm, IPC Medium Density"
  oval 1.4x0.45 smd: 1(-2.95,1.95) 2(-2.95,1.3) 3(-2.95,0.65) 4(-2.95,0) 5(-2.95,-0.65) 6(-2.95,-1.3) 7(-2.95,-1.95) 8(2.95,-1.95) 9(2.95,-1.3) 10(2.95,-0.65) 11(2.95,0) 12(2.95,0.65) 13(2.95,1.3) 14(2.95,1.95)
  silkscreen extent -3.4,-2.55 1.85,2.55, body extent -3.21,-2.5 3.21,2.5, height 1
PW0016A_N [mm] "TSOP, 16-Leads, Body 5x4.4mm, Pitch 0.65mm, IPC Medium Density"
  oval 1.4x0.45 smd: 1(-2.95,2.275) 2(-2.95,1.625) 3(-2.95,0.975) 4(-2.95,0.325) 5(-2.95,-0.325) 6(-2.95,-0.975) 7(-2.95,-1.625) 8(-2.95,-2.275) 9(2.95,-2.275) 10(2.95,-1.625) 11(2.95,-0.975) 12(2.95,-0.325) 13(2.95,0.325) 14(2.95,0.975) 15(2.95,1.625) 16(2.95,2.275)
  silkscreen extent -3.5,-2.55 1.85,2.75, body extent -3.21,-2.5 3.21,2.5, height 1
PZP0100H-MFG [mm]
  rrect33% 1.6x0.3 smd paste-1000 mask+0: 1(-7.6,6) 2(-7.6,5.5) 3(-7.6,5) 4(-7.6,4.5) 5(-7.6,4) 6(-7.6,3.5) 7(-7.6,3) 8(-7.6,2.5) 9(-7.6,2) 10(-7.6,1.5) 11(-7.6,1) 12(-7.6,0.5) 13(-7.6,0) 14(-7.6,-0.5) 15(-7.6,-1) 16(-7.6,-1.5) 17(-7.6,-2) 18(-7.6,-2.5) 19(-7.6,-3) 20(-7.6,-3.5) 21(-7.6,-4) 22(-7.6,-4.5) 23(-7.6,-5) 24(-7.6,-5.5) 25(-7.6,-6) 51(7.6,-6) 52(7.6,-5.5) 53(7.6,-5) 54(7.6,-4.5) 55(7.6,-4) 56(7.6,-3.5) 57(7.6,-3) 58(7.6,-2.5) 59(7.6,-2) 60(7.6,-1.5) 61(7.6,-1) 62(7.6,-0.5) 63(7.6,0) 64(7.6,0.5) 65(7.6,1) 66(7.6,1.5) 67(7.6,2) 68(7.6,2.5) 69(7.6,3) 70(7.6,3.5) 71(7.6,4) 72(7.6,4.5) 73(7.6,5) 74(7.6,5.5) 75(7.6,6)
  rrect33% 0.3x1.6 smd paste-1000 mask+0: 26(-6,-7.6) 27(-5.5,-7.6) 28(-5,-7.6) 29(-4.5,-7.6) 30(-4,-7.6) 31(-3.5,-7.6) 32(-3,-7.6) 33(-2.5,-7.6) 34(-2,-7.6) 35(-1.5,-7.6) 36(-1,-7.6) 37(-0.5,-7.6) 38(0,-7.6) 39(0.5,-7.6) 40(1,-7.6) 41(1.5,-7.6) 42(2,-7.6) 43(2.5,-7.6) 44(3,-7.6) 45(3.5,-7.6) 46(4,-7.6) 47(4.5,-7.6) 48(5,-7.6) 49(5.5,-7.6) 50(6,-7.6) 76(6,7.6) 77(5.5,7.6) 78(5,7.6) 79(4.5,7.6) 80(4,7.6) 81(3.5,7.6) 82(3,7.6) 83(2.5,7.6) 84(2,7.6) 85(1.5,7.6) 86(1,7.6) 87(0.5,7.6) 88(0,7.6) 89(-0.5,7.6) 90(-1,7.6) 91(-1.5,7.6) 92(-2,7.6) 93(-2.5,7.6) 94(-3,7.6) 95(-3.5,7.6) 96(-4,7.6) 97(-4.5,7.6) 98(-5,7.6) 99(-5.5,7.6) 100(-6,7.6)
  rrect1% 12x12 smd paste-1000 mask-1000: 101(0,0)
  silkscreen extent -9.05,-7.1 7.1,7.1, body extent -8.01,-8.01 8.01,8.01, height 1.2
PZP0100K [mm] "TQFP-100"
  rrect33% 1.5x0.3 smd: 1(-7.7,6) 2(-7.7,5.5) 3(-7.7,5) 4(-7.7,4.5) 5(-7.7,4) 6(-7.7,3.5) 7(-7.7,3) 8(-7.7,2.5) 9(-7.7,2) 10(-7.7,1.5) 11(-7.7,1) 12(-7.7,0.5) 13(-7.7,0) 14(-7.7,-0.5) 15(-7.7,-1) 16(-7.7,-1.5) 17(-7.7,-2) 18(-7.7,-2.5) 19(-7.7,-3) 20(-7.7,-3.5) 21(-7.7,-4) 22(-7.7,-4.5) 23(-7.7,-5) 24(-7.7,-5.5) 25(-7.7,-6) 51(7.7,-6) 52(7.7,-5.5) 53(7.7,-5) 54(7.7,-4.5) 55(7.7,-4) 56(7.7,-3.5) 57(7.7,-3) 58(7.7,-2.5) 59(7.7,-2) 60(7.7,-1.5) 61(7.7,-1) 62(7.7,-0.5) 63(7.7,0) 64(7.7,0.5) 65(7.7,1) 66(7.7,1.5) 67(7.7,2) 68(7.7,2.5) 69(7.7,3) 70(7.7,3.5) 71(7.7,4) 72(7.7,4.5) 73(7.7,5) 74(7.7,5.5) 75(7.7,6)
  rrect33% 0.3x1.5 smd: 26(-6,-7.7) 27(-5.5,-7.7) 28(-5,-7.7) 29(-4.5,-7.7) 30(-4,-7.7) 31(-3.5,-7.7) 32(-3,-7.7) 33(-2.5,-7.7) 34(-2,-7.7) 35(-1.5,-7.7) 36(-1,-7.7) 37(-0.5,-7.7) 38(0,-7.7) 39(0.5,-7.7) 40(1,-7.7) 41(1.5,-7.7) 42(2,-7.7) 43(2.5,-7.7) 44(3,-7.7) 45(3.5,-7.7) 46(4,-7.7) 47(4.5,-7.7) 48(5,-7.7) 49(5.5,-7.7) 50(6,-7.7) 76(6,7.7) 77(5.5,7.7) 78(5,7.7) 79(4.5,7.7) 80(4,7.7) 81(3.5,7.7) 82(3,7.7) 83(2.5,7.7) 84(2,7.7) 85(1.5,7.7) 86(1,7.7) 87(0.5,7.7) 88(0,7.7) 89(-0.5,7.7) 90(-1,7.7) 91(-1.5,7.7) 92(-2,7.7) 93(-2.5,7.7) 94(-3,7.7) 95(-3.5,7.7) 96(-4,7.7) 97(-4.5,7.7) 98(-5,7.7) 99(-5.5,7.7) 100(-6,7.7)
  rrect2% 12x12 smd paste-3 mask-3: 101(0,0)
  body extent -8.01,-8.01 8.01,8.01, height 1.2
RESCAXS_EXB-2HV [mm] "Panasonic Resistor Array"
  rect 0.425x0.5 smd mask+0.07: 1(-1.837,-0.75) 8(1.837,-0.75) 9(1.837,0.75) 16(-1.837,0.75)
  rect 0.25x0.5 smd mask+0.07: 2(-1.25,-0.75) 3(-0.75,-0.75) 4(-0.25,-0.75) 5(0.25,-0.75) 6(0.75,-0.75) 7(1.25,-0.75) 10(1.25,0.75) 11(0.75,0.75) 12(0.25,0.75) 13(-0.25,0.75) 14(-0.75,0.75) 15(-1.25,0.75)
  silkscreen extent -2.05,-0.25 2.05,0.25, body extent -1.95,-0.8 1.95,0.8, height 0.55
RNX0012B [mm] "VQFN-HR-12"
  rrect40% 0.6x0.25 smd: 1(-0.9,1.125) 2(-0.9,0.475) 3(-0.9,-0.175) 4(-0.9,-0.675) 8(0.9,-0.675) 9(0.9,-0.175) 10(0.9,0.475) 11(0.9,1.125)
  rrect40% 0.25x0.6 smd: 5(-0.5,-1.4) 6(0,-1.4) 7(0.5,-1.4)
  rrect40% 0.25x1.825 smd paste-0.175: 12(0,0.788)
  body extent -1,-1.5 1,1.5, height 1
SOD-123 [mm] "On Semi recommended land pattern"
  rect 0.915x1.22 smd: 1(-1.637,0) 2(1.637,0)
  silkscreen extent -2.75,-1.17 2.03,1.17, body extent -1.93,-0.9 1.93,0.9, height 1.35
SOD-128 [mm] "SMD, 2-Leads, Body 4x2.7mm, Height 1.1mm"
  rect 1.4x2.1 smd paste-0.1: 1(-2.2,0) 2(2.2,0)
  silkscreen extent -3.45,-1.45 2.95,1.45, body extent -2.5,-1.35 2.5,1.35, height 1.11
SOT-323 [mm] "Diodes Inc recommended land pattern.  2016-02-24"
  rrect21% 0.6x0.47 smd: 1(-0.95,0.65) 2(-0.95,-0.65) 3(0.95,0)
  silkscreen extent -1.14,-1.22 0.77,1.22, body extent -1.13,-1.13 1.12,1.12, height 1.13
TESTPOINT [mil]
  round 80 hole 37.99: 1(0,0)
TI_Stacked_Overlay_Small [mil]
  silkscreen extent -418,-98 418,98
WEEE_Minimum [mil] "WEEElie bin"
  silkscreen extent -95,-172 99,104
WURTH_61300311121 [mm] "Header, 2.54mm, 3x1, TH"
  rrect50% 1.65x1.65 hole 1.15: 1(-2.54,0)
  round 1.65 hole 1.15: 2(0,0) 3(2.54,0)
  body extent -3.81,-1.27 3.81,1.27, height 8.54
WURTH_61300611121 [mm] "Header, 2.54mm, 6x1, TH"
  rrect50% 1.65x1.65 hole 1.15: 1(-6.35,0)
  round 1.65 hole 1.15: 2(-3.81,0) 3(-1.27,0) 4(1.27,0) 5(3.81,0) 6(6.35,0)
  body extent -7.62,-1.27 7.62,1.27, height 8.54
XAL5050 [mm] "CoilCraft XAL5050 5.28 x 5.48 x 5.1 mm"
  rect 1.18x4.44 smd: 1(-1.655,0) 2(1.655,0)
  silkscreen extent -2.75,-2.85 2.75,2.85, body extent -2.74,-2.84 2.74,2.84, height 5.1
XFL4020 [mm] "Coilcraft XFL4020 7/18/12"
  rect 0.98x3.4 smd: 1(-1.181,0) 2(1.181,0)
  silkscreen extent -2.16,-2.16 2.16,2.16, body extent -2.15,-2.15 2.15,2.15, height 2.1
ZEK0324A-MFG [mm]
  round 0.4 smd paste+0 mask-1000: A1(-6.8,6.8) A2(-6,6.8) A3(-5.2,6.8) A4(-4.4,6.8) A5(-3.6,6.8) A6(-2.8,6.8) A7(-2,6.8) A8(-1.2,6.8) A9(-0.4,6.8) A10(0.4,6.8) A11(1.2,6.8) A12(2,6.8) A13(2.8,6.8) A14(3.6,6.8) A15(4.4,6.8) A16(5.2,6.8) A17(6,6.8) A18(6.8,6.8) B1(-6.8,6) B2(-6,6) B3(-5.2,6) B4(-4.4,6) B5(-3.6,6) B6(-2.8,6) B7(-2,6) B8(-1.2,6) B9(-0.4,6) B10(0.4,6) B11(1.2,6) B12(2,6) B13(2.8,6) B14(3.6,6) B15(4.4,6) B16(5.2,6) B17(6,6) B18(6.8,6) C1(-6.8,5.2) C2(-6,5.2) C3(-5.2,5.2) C4(-4.4,5.2) C5(-3.6,5.2) C6(-2.8,5.2) C7(-2,5.2) C8(-1.2,5.2) C9(-0.4,5.2) C10(0.4,5.2) C11(1.2,5.2) C12(2,5.2) C13(2.8,5.2) C14(3.6,5.2) C15(4.4,5.2) C16(5.2,5.2) C17(6,5.2) C18(6.8,5.2) D1(-6.8,4.4) D2(-6,4.4) D3(-5.2,4.4) D4(-4.4,4.4) D5(-3.6,4.4) D6(-2.8,4.4) D7(-2,4.4) D8(-1.2,4.4) D9(-0.4,4.4) D10(0.4,4.4) D11(1.2,4.4) D12(2,4.4) D13(2.8,4.4) D14(3.6,4.4) D15(4.4,4.4) D16(5.2,4.4) D17(6,4.4) D18(6.8,4.4) E1(-6.8,3.6) E2(-6,3.6) E3(-5.2,3.6) E4(-4.4,3.6) E5(-3.6,3.6) E6(-2.8,3.6) E7(-2,3.6) E8(-1.2,3.6) E9(-0.4,3.6) E10(0.4,3.6) E11(1.2,3.6) E12(2,3.6) E13(2.8,3.6) E14(3.6,3.6) E15(4.4,3.6) E16(5.2,3.6) E17(6,3.6) E18(6.8,3.6) F1(-6.8,2.8) F2(-6,2.8) F3(-5.2,2.8) F4(-4.4,2.8) F5(-3.6,2.8) F6(-2.8,2.8) F7(-2,2.8) F8(-1.2,2.8) F9(-0.4,2.8) F10(0.4,2.8) F11(1.2,2.8) F12(2,2.8) F13(2.8,2.8) F14(3.6,2.8) F15(4.4,2.8) F16(5.2,2.8) F17(6,2.8) F18(6.8,2.8) G1(-6.8,2) G2(-6,2) G3(-5.2,2) G4(-4.4,2) G5(-3.6,2) G6(-2.8,2) G7(-2,2) G8(-1.2,2) G9(-0.4,2) G10(0.4,2) G11(1.2,2) G12(2,2) G13(2.8,2) G14(3.6,2) G15(4.4,2) G16(5.2,2) G17(6,2) G18(6.8,2) H1(-6.8,1.2) H2(-6,1.2) H3(-5.2,1.2) H4(-4.4,1.2) H5(-3.6,1.2) H6(-2.8,1.2) H7(-2,1.2) H8(-1.2,1.2) H9(-0.4,1.2) H10(0.4,1.2) H11(1.2,1.2) H12(2,1.2) H13(2.8,1.2) H14(3.6,1.2) H15(4.4,1.2) H16(5.2,1.2) H17(6,1.2) H18(6.8,1.2) J1(-6.8,0.4) J2(-6,0.4) J3(-5.2,0.4) J4(-4.4,0.4) J5(-3.6,0.4) J6(-2.8,0.4) J7(-2,0.4) J8(-1.2,0.4) J9(-0.4,0.4) J10(0.4,0.4) J11(1.2,0.4) J12(2,0.4) J13(2.8,0.4) J14(3.6,0.4) J15(4.4,0.4) J16(5.2,0.4) J17(6,0.4) J18(6.8,0.4) K1(-6.8,-0.4) K2(-6,-0.4) K3(-5.2,-0.4) K4(-4.4,-0.4) K5(-3.6,-0.4) K6(-2.8,-0.4) K7(-2,-0.4) K8(-1.2,-0.4) K9(-0.4,-0.4) K10(0.4,-0.4) K11(1.2,-0.4) K12(2,-0.4) K13(2.8,-0.4) K14(3.6,-0.4) K15(4.4,-0.4) K16(5.2,-0.4) K17(6,-0.4) K18(6.8,-0.4) L1(-6.8,-1.2) L2(-6,-1.2) L3(-5.2,-1.2) L4(-4.4,-1.2) L5(-3.6,-1.2) L6(-2.8,-1.2) L7(-2,-1.2) L8(-1.2,-1.2) L9(-0.4,-1.2) L10(0.4,-1.2) L11(1.2,-1.2) L12(2,-1.2) L13(2.8,-1.2) L14(3.6,-1.2) L15(4.4,-1.2) L16(5.2,-1.2) L17(6,-1.2) L18(6.8,-1.2) M1(-6.8,-2) M2(-6,-2) M3(-5.2,-2) M4(-4.4,-2) M5(-3.6,-2) M6(-2.8,-2) M7(-2,-2) M8(-1.2,-2) M9(-0.4,-2) M10(0.4,-2) M11(1.2,-2) M12(2,-2) M13(2.8,-2) M14(3.6,-2) M15(4.4,-2) M16(5.2,-2) M17(6,-2) M18(6.8,-2) N1(-6.8,-2.8) N2(-6,-2.8) N3(-5.2,-2.8) N4(-4.4,-2.8) N5(-3.6,-2.8) N6(-2.8,-2.8) N7(-2,-2.8) N8(-1.2,-2.8) N9(-0.4,-2.8) N10(0.4,-2.8) N11(1.2,-2.8) N12(2,-2.8) N13(2.8,-2.8) N14(3.6,-2.8) N15(4.4,-2.8) N16(5.2,-2.8) N17(6,-2.8) N18(6.8,-2.8) P1(-6.8,-3.6) P2(-6,-3.6) P3(-5.2,-3.6) P4(-4.4,-3.6) P5(-3.6,-3.6) P6(-2.8,-3.6) P7(-2,-3.6) P8(-1.2,-3.6) P9(-0.4,-3.6) P10(0.4,-3.6) P11(1.2,-3.6) P12(2,-3.6) P13(2.8,-3.6) P14(3.6,-3.6) P15(4.4,-3.6) P16(5.2,-3.6) P17(6,-3.6) P18(6.8,-3.6) R1(-6.8,-4.4) R2(-6,-4.4) R3(-5.2,-4.4) R4(-4.4,-4.4) R5(-3.6,-4.4) R6(-2.8,-4.4) R7(-2,-4.4) R8(-1.2,-4.4) R9(-0.4,-4.4) R10(0.4,-4.4) R11(1.2,-4.4) R12(2,-4.4) R13(2.8,-4.4) R14(3.6,-4.4) R15(4.4,-4.4) R16(5.2,-4.4) R17(6,-4.4) R18(6.8,-4.4) T1(-6.8,-5.2) T2(-6,-5.2) T3(-5.2,-5.2) T4(-4.4,-5.2) T5(-3.6,-5.2) T6(-2.8,-5.2) T7(-2,-5.2) T8(-1.2,-5.2) T9(-0.4,-5.2) T10(0.4,-5.2) T11(1.2,-5.2) T12(2,-5.2) T13(2.8,-5.2) T14(3.6,-5.2) T15(4.4,-5.2) T16(5.2,-5.2) T17(6,-5.2) T18(6.8,-5.2) U1(-6.8,-6) U2(-6,-6) U3(-5.2,-6) U4(-4.4,-6) U5(-3.6,-6) U6(-2.8,-6) U7(-2,-6) U8(-1.2,-6) U9(-0.4,-6) U10(0.4,-6) U11(1.2,-6) U12(2,-6) U13(2.8,-6) U14(3.6,-6) U15(4.4,-6) U16(5.2,-6) U17(6,-6) U18(6.8,-6) V1(-6.8,-6.8) V2(-6,-6.8) V3(-5.2,-6.8) V4(-4.4,-6.8) V5(-3.6,-6.8) V6(-2.8,-6.8) V7(-2,-6.8) V8(-1.2,-6.8) V9(-0.4,-6.8) V10(0.4,-6.8) V11(1.2,-6.8) V12(2,-6.8) V13(2.8,-6.8) V14(3.6,-6.8) V15(4.4,-6.8) V16(5.2,-6.8) V17(6,-6.8) V18(6.8,-6.8)
  silkscreen extent -8.2,-7.55 7.55,7.55, body extent -8.05,-8.05 8.05,8.05, height 0.25

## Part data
C1 C9 C524 C527 C529 C530 C531 C532 C533 C534 C538 C539 C540 C541 C542 C543 C544 C545 C546 C547 C548 C549 C550 C551 C552 C553 C554 C555 C556 C557 C558 C560 C562 C563 C564 C566 C567 C568 C569 C570 C574 C575 C576 C577 C578 C579 C580 C581 C582 C583 C584 C585 C586 C588: library part CMP-0009642-3, "CAP, CERM, 0.01 uF, 10 V, +/- 10%, X7R, AEC-Q200 Grade 1, 0201", Cap_Case=0201_033, Manufacturer=TDK, Supplier Part Number 1=445-12059-1-ND, TempCo=X7R, Tolerance_%=10%, Value1="0.280214 ohm", Value2=10V, ValueDisplayed=0.01uF
C2 C513 C591: library part CMP-0081062-1, "CAP, CERM, 10 µF, 25 V,+/- 5%, X7R, AEC-Q200 Grade 1, 1206", Cap_Case=1206_180, Manufacturer=Kemet, Supplier Part Number 1=399-15734-1-ND, TempCo=X7R, Tolerance_%=5%, Value2=25V, ValueDisplayed=10µF
C3 C7 C8 C10 C11 C13 C14 C15 C20 C21 C22 C25 C28 C29 C30 C33 C40 C42 C44 C46 C47 C49 C50 C51 C52 C55 C59 C506 C514 C515 C520 C522 C523 C528 C593 C594 C595 C596 C597 C598 C599 C602 C603 C606 C608 C609 C614 C617: library part CMP-0006351-2, "CAP, CERM, 0.1 uF, 16 V, +/- 10%, X7R, 0402", Cap_Case=0402, Manufacturer=MuRata, Supplier Part Number 1=490-4759-2-ND, TempCo=X7R, Tolerance_%=10%, Value1=Unknown, Value2=16V, ValueDisplayed=0.1uF
C4 C5 C587 C605: library part CMP-0007136-5, "CAP, CERM, 1 uF, 16 V, +/- 10%, X7R, AEC-Q200 Grade 1, 0603", Cap_Case=0603, Manufacturer=MuRata, Supplier Part Number 1=490-5241-6-ND, TempCo=X7R, Tolerance_%=10%, Value1=Unknown, Value2=16V, ValueDisplayed=1uF
C6 C507 C508 C509 C510 C618 C619 C620 C621 C623 C624 C625 C626 C627 C628: library part CMP-0085851-1, "CAP, CERM, 22 pF, 50 V,+/- 5%, C0G/NP0, 0402", Cap_Case=0402, Manufacturer=Walsin, TempCo=C0G/NP0, Tolerance_%=5%, Value2=50V, ValueDisplayed=22pF
C12 C48: library part CMP-0086096-1, "CAP, CERM, 680 pF, 50 V,+/- 1%, C0G/NP0, AEC-Q200 Grade 1, 0402", Cap_Case=0402, Manufacturer=MuRata, TempCo=C0G/NP0, Tolerance_%=1%, Value2=50V, ValueDisplayed=680pF
C16 C32 C34 C36 C39 C43 C516 C572 C573 C589 C601: library part CMP-0007134-5, "CAP, CERM, 2.2 uF, 6.3 V, +/- 10%, X7R, AEC-Q200 Grade 1, 0603", Cap_Case=0603, Manufacturer=MuRata, Supplier Part Number 1=490-5316-1-ND, TempCo=X7R, Tolerance_%=10%, Value1=Unknown, Value2=6.3V, ValueDisplayed=2.2uF
C17 C18 C19 C27 C525 C526 C535 C536 C537 C559: library part CMP-0008809-2, "CAP, CERM, 22 uF, 6.3 V, +/- 10%, X7R, AEC-Q200 Grade 1, 1206", Cap_Case=1206, Manufacturer=MuRata, Supplier Part Number 1=490-4843-1-ND, TempCo=X7R, Tolerance_%=10%, Value1=Unknown, Value2=6.3V, ValueDisplayed=22uF
C23 C41 C45: library part CMP-0009163-2, "CAP, CERM, 4.7 uF, 50 V, +/- 20%, X7R, AEC-Q200 Grade 1, 1210", Cap_Case=1210, Manufacturer=TDK, Supplier Part Number 1=445-13030-1-ND, TempCo=X7R, Tolerance_%=20%, Value1=Unknown, Value2=50V, ValueDisplayed=4.7uF
C24 C35 C517 C612: library part CMP-0093813-1, "Cap Ceramic 10uF 6.3V X7R 10% Pad SMD 0805 +125°C Automotive T/R", Manufacturer="TDK Corporation", Operating Temperature Range="-55°C to +125°C", TempCo=15%, Temperature Characteristic=X7R, Tolerance_%=0.1%, ValueDisplayed=10uF
C26 C561: library part CMP-0095622-1, "Cap Ceramic 33pF 50V C0G 5% Pad SMD 0603 +125°C Automotive T/R", Manufacturer=TDK, Operating Temperature Range="-55°C to +125°C", TempCo=30ppm/°C, Temperature Characteristic=C0G, Tolerance_%=0.05%, ValueDisplayed=33pF
C31 C37: library part CMP-0095620-1, "C0603 22,000 pF X7R 30ppm/°C 10.00% 100 V", Digikey Part Number=399-6872-2-ND, Manufacturer=KEMET, Mouser Part Number=80-C0603C223K1RAUTO, Operating Temperature Range="-55°C to +125°C", TempCo=30ppm/°C, Temperature Characteristic=X7R, Tolerance_%=0.1%, ValueDisplayed="22,000 pF"
C38: library part CMP-0860440-1, "CAP, CERM, 0.1 µF, 100 V,+/- 10%, X7R, AEC-Q200 Grade 1, 0805", Cap_Case=0805, Manufacturer=MuRata, TempCo=X7R, Tolerance_%=10%, Value2=100V, ValueDisplayed=0.1µF
C53 C54: library part CMP-0007140-4, "CAP, CERM, 0.22 uF, 25 V, +/- 10%, X7R, AEC-Q200 Grade 1, 0603", Cap_Case=0603, Manufacturer=MuRata, Supplier Part Number 1=490-4935-1-ND, TempCo=X7R, Tolerance_%=10%, Value1=Unknown, Value2=25V, ValueDisplayed=0.22uF
C56 C519 C611: library part CMP-0093287-1, "Ceramic Capacitor for Automotive 10nF ±10% 50VDC X7R 0402 Paper T/R", Manufacturer=Murata, Operating Temperature Range="-55°C to +125°C", TempCo=15%, Temperature Characteristic=X7R, Tolerance_%=0.1%, ValueDisplayed=10nF
C57 C58 C622: library part CMP-0006317-2, "CAP, CERM, 2200 pF, 50 V, +/- 10%, X7R, AEC-Q200 Grade 1, 0402", Cap_Case=0402, Manufacturer=TDK, Supplier Part Number 1=445-5606-1-ND, TempCo=X7R, Tolerance_%=10%, Value1="1.07794 ohm", Value2=50V, ValueDisplayed=2200pF
C500 C501 C502 C503 C504 C505 C511: library part CMP-0079095-1, "CAP, CERM, 0.1 µF, 50 V,+/- 10%, X7R, AEC-Q200 Grade 1, 0603", Cap_Case=0603, Manufacturer=AVX, Supplier Part Number 1=478-3540-1-ND, TempCo=X7R, Tolerance_%=10%, Value2=50V, ValueDisplayed=0.1µF
C512 C565 C590 C592 C600 C604 C615: library part CMP-0007975-2, "CAP, CERM, 2.2 uF, 25 V, +/- 10%, X7R, AEC-Q200 Grade 1, 0805", Cap_Case=0805, Manufacturer=TDK, Supplier Part Number 1=445-6965-1-ND, TempCo=X7R, Tolerance_%=10%, Value1=Unknown, Value2=25V, ValueDisplayed=2.2uF
C518 C521: library part CMP-0860829-1, "CAP, CERM, 15 pF, 50 V,+/- 5%, C0G/NP0, AEC-Q200 Grade 1, 0402", Cap_Case=0402, Manufacturer=TDK, TempCo=C0G/NP0, Tolerance_%=5%, Value2=50V, ValueDisplayed=15pF
C571: library part CMP-0007078-4, "CAP, CERM, 0.1 uF, 50 V, +/- 10%, X7R, AEC-Q200 Grade 1, 0603", Cap_Case=0603, Manufacturer=TDK, Supplier Part Number 1=445-5666-1-ND, TempCo=X7R, Tolerance_%=10%, Value1="0.0296 ohm", Value2=50V, ValueDisplayed=0.1uF
C607: library part CMP-0006318-2, "CAP, CERM, 330 pF, 50 V, +/- 10%, X7R, AEC-Q200 Grade 1, 0402", Cap_Case=0402, Manufacturer=TDK, Supplier Part Number 1=445-6887-1-ND, TempCo=X7R, Tolerance_%=10%, Value1="6.53276 ohm", Value2=50V, ValueDisplayed=330pF
C610: library part CMP-0008776-2, "CAP, CERM, 0.47 uF, 50 V, +/- 10%, X7R, AEC-Q200 Grade 1, 1206", Cap_Case=1206_180, Manufacturer=TDK, Supplier Part Number 1=445-5700-1-ND, TempCo=X7R, Tolerance_%=10%, Value1="0.009426 ohm", Value2=50V, ValueDisplayed=0.47uF
C613 C616: library part CMP-0083705-1, "CAP, CERM, 1 µF, 50 V,+/- 10%, X7R, AEC-Q200 Grade 1, 0805", Cap_Case=0805, Manufacturer=AVX, Supplier Part Number 1=478-9557-1-ND, TempCo=X7R, Tolerance_%=10%, Value2=50V, ValueDisplayed=1µF
D1: library part CMP-0028783-3, "Diode, Schottky, 100 V, 3 A, AEC-Q101, SOD-128", Manufacturer=Nexperia, Value1=3A, Value2=0.77V
D2 D3: library part CMP-0002830-3, "LED, Green, SMD", Color=green, Manufacturer=Lite-On, Value1=W, Value2=2.1V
